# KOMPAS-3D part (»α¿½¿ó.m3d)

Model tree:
1. Эскиз:1
2. Операция выдавливания:1
     Расстояние 1 = 10
3. Скругление:1
     Радиус = 8
4. Эскиз:2
5. Вырезать элемент выдавливания:1
     Расстояние 1 = 0.5

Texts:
  stalker61
  Сплав АЛ8  ГОСТ 1583-93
